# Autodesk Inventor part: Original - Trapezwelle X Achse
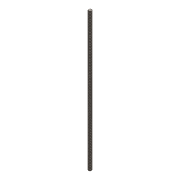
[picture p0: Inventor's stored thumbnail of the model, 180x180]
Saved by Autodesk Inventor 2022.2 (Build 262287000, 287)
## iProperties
Created: 2024-09
Part Number: Original - Trapezwelle X Achse
Material: Generico
Document SubType Name: Modeling
Designer: 18907419
Density: 1 g/cm^3
Appearance: Default
Author: 18907419
Revision Number: ANY
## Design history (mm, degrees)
feature "Schnitt-Rotation1"
sketch "Schizzo1"
  geometry: L1 (-3.375, 11.321)-(23.093, 11.321); L2 (23.093, 11.321)-(23.093, -10.061); L3 (23.093, -10.061)-(-3.375, -10.061); L4 (-3.375, -10.061)-(-3.375, 11.321); 1 further point
  constraints: 8 end point
extrude "Estrusione1" cut sketch "Schizzo1" distance "d0" = 10; taper "d1" = 0 deg
sketch "Schizzo2"
  geometry: L1 (4, 16.716)-(4, 15.834) reference; L2 (4, 18.716)-(4, 17.834) reference; L3 (3.5, 15.508)-(3.5, 15.042) reference; L4 (4, 2.716)-(4, 1.834) reference; L5 (3.2, 0)-(-3.2, 0) reference; 5 further points
  constraints: 4 midpoint
  dimensions: "d2" = 2 distance of point (4, 16.275) point (4, 18.275) (derived); "d3" = 0.5 distance between parallel lines of L3 L1 (derived); "d4" = 4 horizontal distance of point (4, 2.275) point (0, 0) (derived)
node "Solido1"
